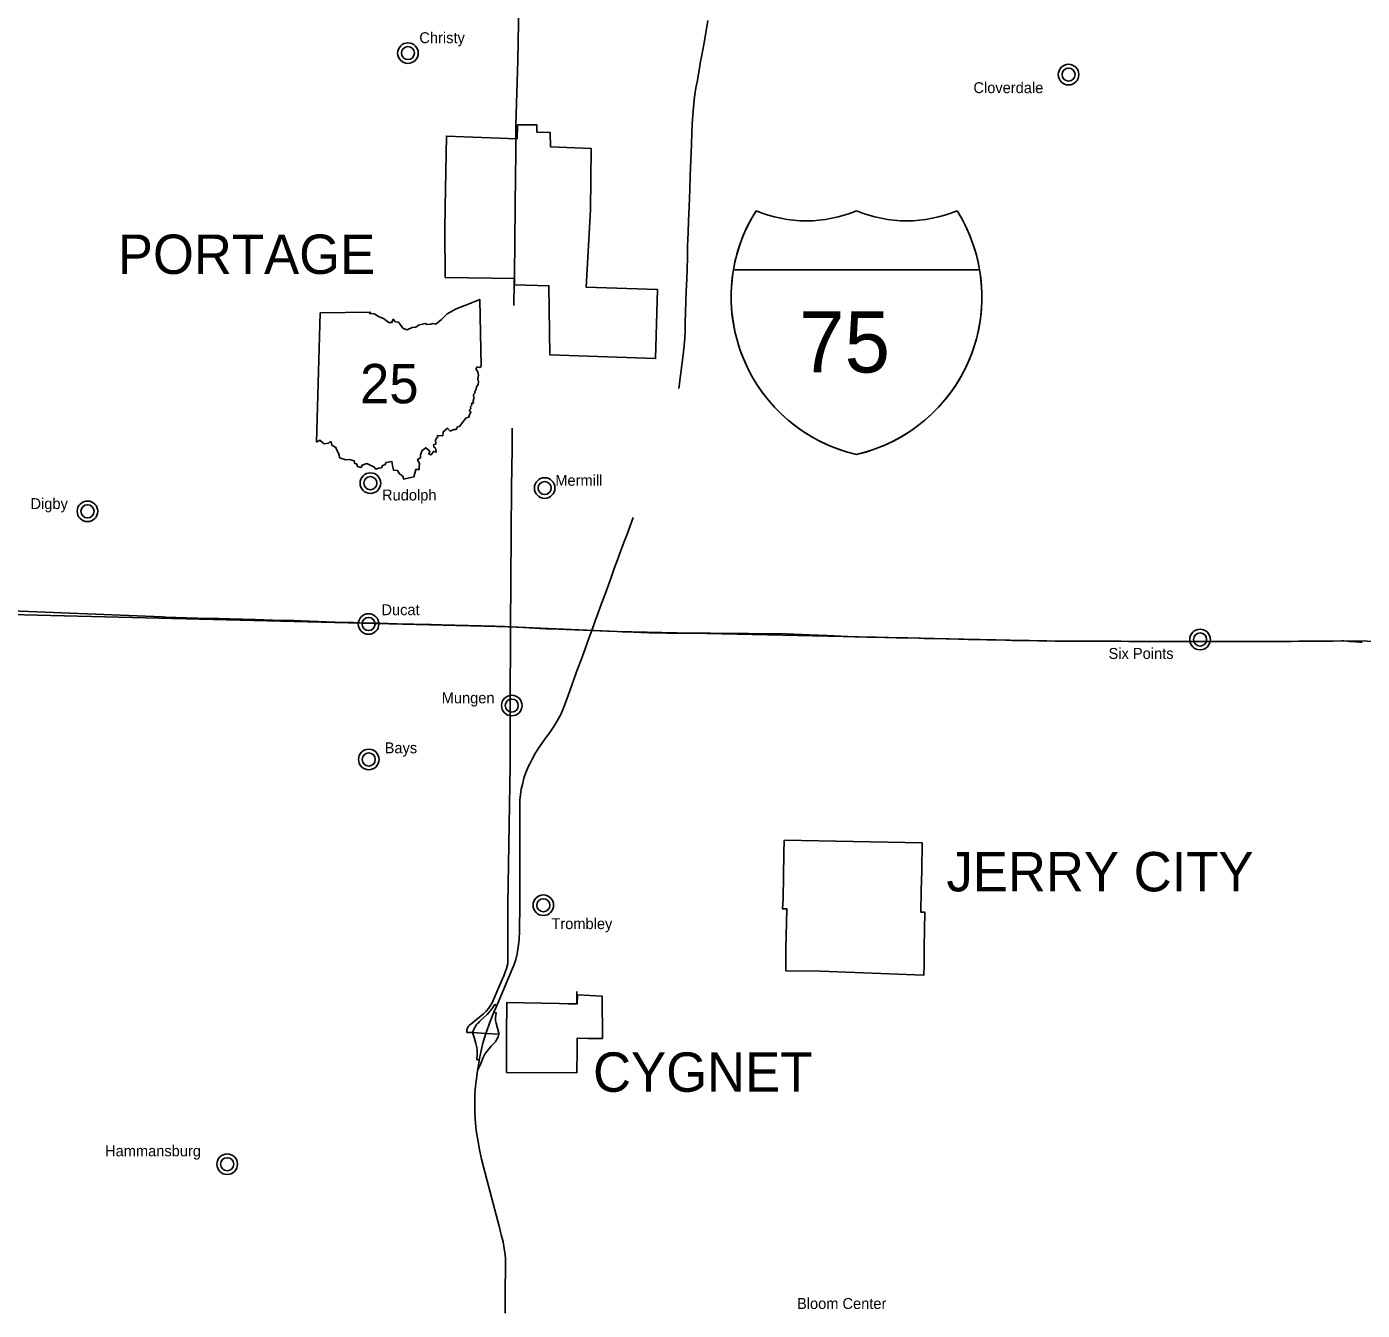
# Model space of a CAD drawing. Extents: x 0 to 851, y 0 to 440.
# Drawn here: x 282.5 to 367.7, y 111.8 to 193.8 of the extents above; entities that cross this region are included whole.
import ezdxf

# ---------------------------------------------------------------- set-up
doc = ezdxf.new("R2010")
doc.units = 0
for name, color, linetype in [('DV_X_Corp_Line', 7, 'Continuous'), ('GM_X_Corporation_Text', 7, 'Continuous'), ('GM_X_Interstate_Route', 7, 'Continuous'), ('GM_X_State_Route', 7, 'Continuous'), ('PV_P_Text', 7, 'Continuous'), ('RD_P_Fence', 7, 'Continuous')]:
    doc.layers.add(name, color=color, linetype=linetype)

msp = doc.modelspace()

# ---------------------------------------------------------------- linework, layer by layer
at = {"layer": 'DV_X_Corp_Line'}
for points in [[(309.156, 180.793), (309.185, 182.222), (309.259, 186.766), (313.776, 186.601), (313.806, 187.486), (315.035, 187.48), (315.042, 187.025), (315.891, 186.998), (315.897, 186.088), (318.504, 185.969), (318.463, 182.066), (318.183, 177.128), (322.74, 176.974), (322.618, 172.57), (315.854, 172.809), (315.801, 177.213), (313.602, 177.265), (313.604, 177.685), (309.185, 177.753)], [(330.834, 141.826), (339.637, 141.65), (339.603, 139.875), (339.577, 138.632), (339.551, 137.225), (339.811, 137.22), (339.771, 135.004), (339.751, 133.854), (339.743, 133.211), (335.342, 133.388), (333.141, 133.468), (330.926, 133.491), (330.926, 134.864), (331, 137.432), (330.727, 137.44), (330.752, 138.087), (330.808, 141.003)], [(313.093, 126.99), (313.104, 129.388), (313.113, 131.456), (316.452, 131.39), (316.485, 131.396), (317.011, 131.387), (317.616, 131.382), (317.633, 131.943), (319.202, 131.858), (319.217, 129.16), (318.894, 129.165), (318.292, 129.173), (317.605, 129.181), (317.604, 128.508), (317.596, 126.979)]]:
    msp.add_lwpolyline(points, close=True, dxfattribs=at)
msp.add_lwpolyline([(317.595, 131.372), (317.598, 132.163)], dxfattribs=at)
for centre, radius in [((306.807, 192.066), 0.658), ((306.807, 192.066), 0.417), ((348.979, 190.693), 0.658), ((348.979, 190.693), 0.417), ((304.408, 164.615), 0.658), ((304.408, 164.615), 0.417), ((315.535, 164.303), 0.658), ((315.535, 164.303), 0.417), ((286.348, 162.817), 0.658), ((286.348, 162.817), 0.417), ((304.292, 155.623), 0.658), ((304.292, 155.623), 0.417), ((357.374, 154.633), 0.658), ((357.374, 154.633), 0.417), ((313.436, 150.418), 0.658), ((313.436, 150.418), 0.417), ((304.306, 146.975), 0.658), ((304.306, 146.975), 0.417), ((315.45, 137.673), 0.658), ((315.45, 137.673), 0.417), ((295.266, 121.141), 0.658), ((295.266, 121.141), 0.417)]:
    msp.add_circle(centre, radius, dxfattribs=at)
at = {"layer": 'GM_X_Interstate_Route'}
for points in [[(324.103, 170.649), (324.39, 172.98), (324.431, 173.433), (324.472, 173.872), (324.496, 174.305), (324.509, 174.899), (324.529, 175.506), (324.554, 176.207), (324.578, 176.841), (324.601, 177.65), (324.629, 178.301), (324.644, 179.019), (324.663, 179.77), (324.697, 180.606), (324.719, 181.358), (324.751, 182.27), (324.795, 183.341), (324.833, 184.233), (324.869, 185.213), (324.906, 186.226), (324.928, 186.948), (324.961, 187.559), (324.997, 188.112), (325.042, 188.595), (325.086, 189.054), (325.116, 189.43), (325.193, 189.858), (325.288, 190.324), (325.358, 190.746), (325.435, 191.225), (325.468, 191.427), (325.563, 191.945), (325.686, 192.617), (325.813, 193.357), (325.958, 194.139)], [(312.435, 131.167), (312.481, 131.276), (312.793, 132.01), (313.17, 132.884), (313.59, 133.893), (313.689, 134.206), (313.773, 134.56), (313.871, 135.153), (313.903, 135.502), (313.921, 136.016), (313.945, 137.75), (313.958, 144.41), (313.987, 144.719), (314.043, 145.077), (314.112, 145.382), (314.215, 145.773), (314.339, 146.143), (314.461, 146.444), (314.532, 146.6), (314.583, 146.704), (314.735, 147), (314.929, 147.36), (315.142, 147.689), (315.358, 147.994), (315.592, 148.326), (315.859, 148.701), (316.079, 149.013), (316.234, 149.253), (316.403, 149.542), (316.559, 149.842), (316.716, 150.202), (316.881, 150.646), (317.053, 151.117), (317.253, 151.664), (317.443, 152.205), (317.636, 152.739), (317.857, 153.347), (318.11, 154.034), (318.31, 154.589), (318.539, 155.208), (318.745, 155.77), (318.955, 156.341), (319.163, 156.925), (319.397, 157.523), (319.58, 158.06), (319.78, 158.598), (319.977, 159.162), (320.191, 159.723), (320.374, 160.26), (320.592, 160.831), (320.792, 161.368), (321.174, 162.433)], [(311.815, 129.587), (312.005, 130.151), (312.295, 130.839), (312.435, 131.167)], [(313.009, 111.635), (313.013, 113.295), (313.026, 114.394), (313.026, 115.129), (313.005, 115.354), (312.958, 115.765), (312.877, 116.177), (312.763, 116.631), (312.621, 117.187), (311.863, 120.08), (311.504, 121.466), (311.368, 122.076), (311.29, 122.572), (311.171, 123.29), (311.103, 123.996), (311.073, 124.529), (311.073, 125.009), (311.084, 125.639), (311.114, 126.127), (311.173, 126.586), (311.241, 127.129), (311.3, 127.458), (311.352, 127.784), (311.452, 128.299), (311.591, 128.872), (311.782, 129.489), (311.815, 129.587)]]:
    msp.add_lwpolyline(points, dxfattribs=at)
at = {"layer": 'GM_X_State_Route'}
for points in [[(313.703, 187.487), (313.813, 191.603), (313.884, 195.2), (313.891, 195.752)], [(313.684, 186.204), (313.69, 186.965)], [(313.69, 186.965), (313.691, 187.05), (313.703, 187.487)], [(313.663, 183.666), (313.684, 186.204)], [(313.657, 182.905), (313.663, 183.666)], [(313.639, 180.812), (313.648, 181.474), (313.652, 182.144), (313.656, 182.805), (313.657, 182.905)], [(313.629, 180.102), (313.639, 180.812)], [(313.599, 177.882), (313.629, 180.102)], [(313.573, 175.964), (313.593, 177.438)], [(313.593, 177.438), (313.599, 177.882)], [(313.185, 137.585), (313.185, 137.761), (313.325, 146.591), (313.336, 150.166), (313.351, 155.438), (313.417, 164.35), (313.45, 166.775), (313.468, 168.128)], [(280.442, 156.517), (291.123, 156.074)], [(291.123, 156.074), (291.344, 156.067), (292.662, 156.027), (293.368, 156), (294.737, 155.966), (295.467, 155.952), (297.052, 155.901), (297.612, 155.892), (298.15, 155.877), (298.669, 155.858), (299.528, 155.841), (299.99, 155.824), (302.164, 155.742), (302.801, 155.715), (303.314, 155.715), (303.729, 155.703), (304.489, 155.684), (305.007, 155.669), (305.528, 155.655), (306.115, 155.638), (306.652, 155.619), (307.187, 155.614), (307.758, 155.599), (308.293, 155.584), (308.943, 155.567), (309.358, 155.551), (309.791, 155.545), (312.362, 155.483), (312.697, 155.471), (312.97, 155.458), (313.223, 155.444), (313.351, 155.438)], [(313.351, 155.438), (314.152, 155.394), (315.595, 155.32), (315.855, 155.32), (316.9, 155.277)], [(316.9, 155.277), (318.539, 155.208), (319.06, 155.185), (319.538, 155.166), (320.168, 155.14), (320.49, 155.127)], [(320.49, 155.127), (320.648, 155.12), (321.231, 155.094), (321.702, 155.075), (322.197, 155.062), (322.632, 155.057), (323.324, 155.043), (324.919, 155.036), (325.58, 155.029), (326.135, 155.029), (330.957, 154.988), (332.432, 154.923), (333.569, 154.892), (335.34, 154.811), (335.492, 154.807), (336.107, 154.791), (336.698, 154.776), (337.273, 154.765), (337.969, 154.75), (338.715, 154.735), (339.521, 154.714), (339.755, 154.709)], [(339.755, 154.709), (340.294, 154.698), (341.137, 154.669), (341.961, 154.652), (342.579, 154.639), (343.157, 154.628), (343.752, 154.616), (344.33, 154.604), (344.955, 154.585), (345.368, 154.574), (345.97, 154.569), (346.484, 154.566), (347.015, 154.556), (347.597, 154.541), (348.118, 154.531), (348.625, 154.525), (349.173, 154.524), (349.772, 154.529), (350.397, 154.533), (350.945, 154.532), (351.624, 154.525), (352.344, 154.52), (352.828, 154.514), (353.033, 154.514), (353.457, 154.515), (354.112, 154.515), (354.852, 154.512), (355.423, 154.511), (356.621, 154.514), (357.249, 154.515), (357.444, 154.515), (357.767, 154.515), (358.305, 154.511), (358.897, 154.513), (359.411, 154.51), (359.969, 154.512), (360.605, 154.509), (361.361, 154.507), (361.953, 154.508), (362.531, 154.507), (363.181, 154.514), (363.682, 154.518), (364.126, 154.523), (364.667, 154.526), (365.299, 154.53), (365.874, 154.536), (366.426, 154.542), (366.461, 154.542), (366.547, 154.542), (366.913, 154.516), (367.309, 154.492), (367.557, 154.472), (367.732, 154.471)], [(313.178, 134.061), (313.184, 137.443), (313.185, 137.585)], [(312.606, 129.445), (311.782, 129.489), (310.943, 129.538), (310.569, 129.554), (310.573, 129.744), (310.602, 129.835), (310.653, 129.921), (310.719, 129.99), (310.821, 130.085), (311.636, 130.735), (311.808, 130.906), (311.959, 131.087), (312.078, 131.264), (312.178, 131.441), (312.678, 132.597), (312.937, 133.172), (313.104, 133.629), (313.177, 133.963), (313.178, 134.061)], [(312.481, 131.276), (312.347, 131.329), (312.273, 131.203), (312.179, 131.07), (312.106, 130.97), (311.997, 130.841), (311.858, 130.695), (311.466, 130.335), (311.368, 130.247), (311.302, 130.173), (311.232, 130.104), (311.172, 130.028), (311.116, 129.938), (311.059, 129.839), (310.955, 129.589), (310.943, 129.538)], [(312.606, 129.445), (312.603, 129.503), (312.428, 130.14), (312.406, 130.306), (312.399, 130.483), (312.417, 130.64), (312.443, 130.8), (312.295, 130.839)], [(310.943, 129.538), (310.952, 129.488), (311.051, 129.155), (311.147, 128.849), (311.205, 128.59), (311.226, 128.41), (311.231, 128.217), (311.229, 128.083), (311.212, 127.924), (311.198, 127.816), (311.352, 127.784)], [(311.241, 127.129), (311.463, 127.544), (311.528, 127.741), (311.604, 127.953), (311.714, 128.163), (311.835, 128.345), (312.126, 128.681), (312.387, 128.957), (312.491, 129.118), (312.557, 129.262), (312.606, 129.445)]]:
    msp.add_lwpolyline(points, dxfattribs=at)
at = {"layer": 'PV_P_Text'}
for p, q in [((327.587, 178.238), (343.302, 178.238)), ((343.302, 178.238), (327.587, 178.238)), ((343.302, 178.238), (327.587, 178.238)), ((300.975, 167.232), (301.206, 175.481)), ((300.975, 167.232), (301.206, 175.481))]:
    msp.add_line(p, q, dxfattribs=at)
for points in [[(301.206, 175.481), (304.406, 175.534), (304.356, 175.435), (304.658, 175.414), (304.979, 175.237), (305.25, 175.126), (305.582, 174.864), (305.781, 174.867), (305.865, 175.082), (306.017, 174.916), (306.197, 174.886), (306.509, 174.492), (306.767, 174.406), (307.075, 174.541), (307.306, 174.564), (307.474, 174.697), (307.913, 174.812), (308.036, 174.743), (308.268, 174.757), (308.385, 174.808), (308.588, 174.762), (308.945, 175.062), (309.313, 175.416), (309.878, 175.75), (310.722, 176.066), (311.39, 176.348), (311.486, 172.068)], [(301.206, 175.481), (304.406, 175.534), (304.356, 175.435), (304.658, 175.414), (304.979, 175.237), (305.25, 175.126), (305.582, 174.864), (305.781, 174.867), (305.865, 175.082), (306.017, 174.916), (306.197, 174.886), (306.509, 174.492), (306.767, 174.406), (307.075, 174.541), (307.306, 174.564), (307.474, 174.697), (307.913, 174.812), (308.036, 174.743), (308.268, 174.757), (308.385, 174.808), (308.588, 174.762), (308.945, 175.062), (309.313, 175.416), (309.878, 175.75), (310.722, 176.066), (311.39, 176.348), (311.486, 172.068)], [(311.486, 172.068), (311.388, 172.008), (311.234, 172.036), (311.131, 171.916), (311.259, 171.716), (311.319, 171.504), (311.266, 171.271), (311.318, 171.079), (311.282, 170.918), (311.186, 170.757), (311.153, 170.605), (311.071, 170.444), (311.078, 170.354), (310.999, 170.282), (311.014, 170.014), (310.974, 169.866), (310.988, 169.738), (310.861, 169.705), (310.89, 169.599), (310.809, 169.517), (310.827, 169.377), (310.735, 169.287), (310.824, 169.107), (310.753, 169.051), (310.694, 168.832), (310.531, 168.788), (310.206, 168.388), (310.091, 168.237), (309.962, 168.2), (309.891, 168.045), (309.732, 168.044), (309.491, 167.937), (309.336, 168.122), (309.064, 167.899), (309.032, 167.642), (308.688, 167.65), (308.702, 167.52), (308.625, 167.482), (308.555, 167.352), (308.595, 167.12), (308.434, 167.061), (308.454, 166.927), (308.557, 166.845), (308.603, 166.588), (308.432, 166.64), (308.291, 166.423), (308.147, 166.474), (308.194, 166.658), (307.95, 166.878), (307.72, 166.701), (307.599, 166.419), (307.598, 166.229), (307.426, 166.115), (307.536, 165.846), (307.516, 165.662), (307.52, 165.486), (307.305, 165.492), (307.175, 165.019)], [(311.486, 172.068), (311.388, 172.008), (311.234, 172.036), (311.131, 171.916), (311.259, 171.716), (311.319, 171.504), (311.266, 171.271), (311.318, 171.079), (311.282, 170.918), (311.186, 170.757), (311.153, 170.605), (311.071, 170.444), (311.078, 170.354), (310.999, 170.282), (311.014, 170.014), (310.974, 169.866), (310.988, 169.738), (310.861, 169.705), (310.89, 169.599), (310.809, 169.517), (310.827, 169.377), (310.735, 169.287), (310.824, 169.107), (310.753, 169.051), (310.694, 168.832), (310.531, 168.788), (310.206, 168.388), (310.091, 168.237), (309.962, 168.2), (309.891, 168.045), (309.732, 168.044), (309.491, 167.937), (309.336, 168.122), (309.064, 167.899), (309.032, 167.642), (308.688, 167.65), (308.702, 167.52), (308.625, 167.482), (308.555, 167.352), (308.595, 167.12), (308.434, 167.061), (308.454, 166.927), (308.557, 166.845), (308.603, 166.588), (308.432, 166.64), (308.291, 166.423), (308.147, 166.474), (308.194, 166.658), (307.95, 166.878), (307.72, 166.701), (307.599, 166.419), (307.598, 166.229), (307.426, 166.115), (307.536, 165.846), (307.516, 165.662), (307.52, 165.486), (307.305, 165.492), (307.175, 165.019)], [(307.175, 165.019), (306.801, 164.928), (306.542, 164.874), (306.45, 165.089), (306.265, 165.203), (306.144, 165.419), (305.878, 165.449), (305.815, 165.746), (305.785, 165.987), (305.421, 165.928), (305.321, 165.78), (305.192, 165.741), (305.117, 165.592), (304.941, 165.58), (304.753, 165.509), (304.629, 165.655), (304.32, 165.802), (304.181, 165.877), (303.89, 165.76), (303.828, 165.621), (303.596, 165.682), (303.542, 165.837), (303.402, 165.884), (303.371, 166.048), (303.072, 166.135), (302.842, 166.101), (302.438, 166.233), (302.414, 166.449), (302.276, 166.712), (302.204, 166.895), (301.949, 167.035), (301.897, 167.252), (301.816, 167.246), (301.741, 167.158), (301.457, 167.117), (301.344, 167.206), (301.185, 167.358), (300.975, 167.232)], [(307.175, 165.019), (306.801, 164.928), (306.542, 164.874), (306.45, 165.089), (306.265, 165.203), (306.144, 165.419), (305.878, 165.449), (305.815, 165.746), (305.785, 165.987), (305.421, 165.928), (305.321, 165.78), (305.192, 165.741), (305.117, 165.592), (304.941, 165.58), (304.753, 165.509), (304.629, 165.655), (304.32, 165.802), (304.181, 165.877), (303.89, 165.76), (303.828, 165.621), (303.596, 165.682), (303.542, 165.837), (303.402, 165.884), (303.371, 166.048), (303.072, 166.135), (302.842, 166.101), (302.438, 166.233), (302.414, 166.449), (302.276, 166.712), (302.204, 166.895), (301.949, 167.035), (301.897, 167.252), (301.816, 167.246), (301.741, 167.158), (301.457, 167.117), (301.344, 167.206), (301.185, 167.358), (300.975, 167.232)]]:
    msp.add_lwpolyline(points, dxfattribs=at)
for centre, radius, start, end in [((337.769, 176.507), 10.328, 147.82161, 256.99413), ((337.123, 176.686), 9.662, 146.65397, 170.75899), ((332.236, 189.598), 8.241, 247.08482, 292.91053), ((332.236, 189.598), 8.241, 247.08482, 292.91053), ((333.12, 176.507), 10.328, 283.00654, 32.17868), ((338.653, 189.6), 8.243, 247.09162, 292.90836), ((338.653, 189.6), 8.243, 247.09162, 292.90836), ((333.12, 176.507), 10.328, 9.64753, 32.17902), ((337.768, 176.507), 10.328, 170.35136, 256.9967), ((333.141, 176.503), 10.308, 282.76665, 9.68983)]:
    msp.add_arc(centre, radius, start, end, dxfattribs=at)
at = {"layer": 'RD_P_Fence'}
msp.add_line((226.973, 157.589), (313.351, 155.438), dxfattribs=at)
msp.add_lwpolyline([(378.533, 154.38), (366.547, 154.542), (361.361, 154.507), (356.621, 154.514), (348.118, 154.531), (324.919, 155.036), (320.168, 155.14), (313.351, 155.438)], dxfattribs=at)

# ---------------------------------------------------------------- texts
at = {"layer": 'DV_X_Corp_Line'}
for s, height, p in [('Christy', 0.6979, (307.534, 192.7)), ('Cloverdale', 0.6979, (342.906, 189.511)), ('Mermill', 0.6979, (316.214, 164.448)), ('Rudolph', 0.6979, (305.152, 163.508)), ('Digby', 0.6979, (282.71, 162.959)), ('Ducat', 0.6979, (305.114, 156.186)), ('Six Points', 0.6979, (351.532, 153.396)), ('Mungen', 0.6979, (308.962, 150.563)), ('Bays', 0.6979, (305.32, 147.369)), ('Trombley', 0.6979, (315.964, 136.147)), ('Hammansburg', 0.69792, (287.471, 121.643)), ('Bloom Center', 0.69792, (331.644, 111.901))]:
    msp.add_text(s, height=height, rotation=0.00001, dxfattribs=at).set_placement(p)
at = {"layer": 'GM_X_Corporation_Text'}
for s, p in [('PORTAGE', (288.287, 177.971)), ('JERRY CITY', (341.187, 138.557)), ('CYGNET', (318.624, 125.765))]:
    msp.add_text(s, height=2.5126, rotation=0.00001, dxfattribs=at).set_placement(p)
at = {"layer": 'PV_P_Text'}
for s, height, p in [('75', 3.9007, (331.78, 171.679)), ('25', 2.5126, (303.747, 169.713))]:
    msp.add_text(s, height=height, dxfattribs=at).set_placement(p)

doc.saveas('drawing.dxf')
